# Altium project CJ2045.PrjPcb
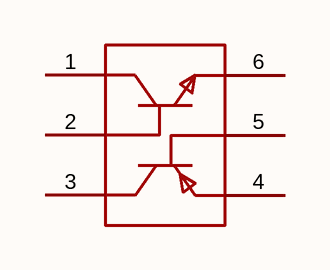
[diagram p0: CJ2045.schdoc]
1 sheet, 1 parts. Net scope: global (net labels, ports and power ports of the same name join across sheets).

## Sheet CJ2045.schdoc
size 127 x 101 mm

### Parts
Q?  cj2045  [SOT-23-6_L2.9-W1.6-P0.95-LS2.8-BR]  (value not drawn)

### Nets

Not connected (* = marked no-connect by the designer): Q? 1(E1) 2(B1) 3(C2) 4(E2) 5(B2) 6(C1)

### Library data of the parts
Q? = cj2045: 晶体管类型:NPN+PNP;集电极电流(Ic):1.5A;集射极击穿电压(Vceo):30V;耗散功率(Pd):350mW;直流电流增益(hFE):180;; Manufacturer: CJ(江苏长电/长晶); AddInBom: yes; ModelId: 18da8f6c14a34920b3e136b5c401a119; ModelName: SOT-23-6_L2.9-W1.6-H1.5-LS2.8-P0.95; ModelTransform: 110.73671,114.173,0,180,0,0,0.001,-0.003,0; Current - Collector(Ic): 1.5A; Collector - Emitter Voltage VCEO: 30V; Pd - Power Dissipation: 350mW; DC Current Gain: 180; Current - Collector Cutoff: 20nA; Vce Saturation(VCE(sat)): 375mV; Emitter-Base Voltage(Vebo): 7V; Number: 1个NPN+1个PNP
